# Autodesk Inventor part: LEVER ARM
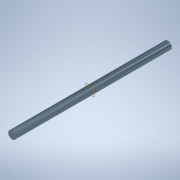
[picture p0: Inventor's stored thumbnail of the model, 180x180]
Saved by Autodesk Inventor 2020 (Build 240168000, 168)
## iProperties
Part Number: LEVER ARM
Document SubType Name: Modeling
Created: 2003-11
Designer: Autodesk, Inc.
Manufacturer: Standard
Standards Organization: Custom
Mass: 252.581 g
Surface Area: 103.875 cm^2
Volume: 32.1759 cm^3
Density: 7.85 g/cm^3
Material: Steel, Mild
Appearance: Nickel (Bright)
Control State: 0
Master: False
Checked Out: False
Shininess: 64.0
Length Units: 11272
Angle Units: 11279
Time Units: 11290
Mass Units: 11286
Length Display Precision: 3
Angle Display Precision: 2
Compacted: True
Density: 0.0
Volumn: 0.0
Area: 0.0
PropertySet Name: Model Information
Author: Autodesk, Inc.
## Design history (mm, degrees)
sketch "Sketch1"
  geometry: C1 r 6.35 at (0, 0); 1 further point
  constraints: 1 centre point, 1 coincident
  dimensions: "d0" = 12.7 diameter of C1
extrude "Extrusion1" new body sketch "Sketch1" distance "d1" = 254; taper "d2" = 0 deg
workplane "Work Plane1"
body "Solid1"
